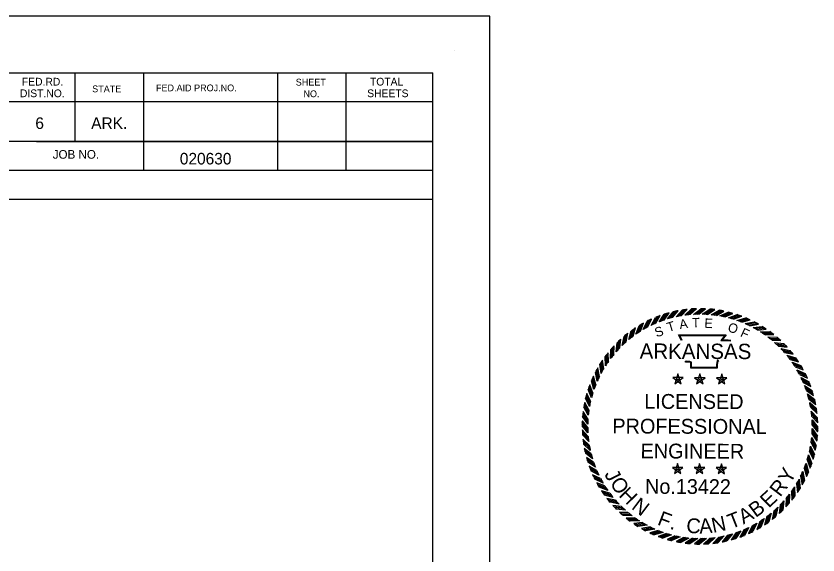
# Model space of a CAD drawing. Extents: x 759422 to 1402140, y 1662254 to 1956530.
# Drawn here: x 1401731.3 to 1402137.5, y 1956257.2 to 1956530.4 of the extents above; entities that cross this region are included whole.
import ezdxf

# ---------------------------------------------------------------- set-up
doc = ezdxf.new("R2010")
doc.units = 0
doc.layers.add('1', color=7, linetype='Continuous')
doc.layers.add('Default', color=7, linetype='Continuous')

# ---------------------------------------------------------------- blocks, each defined once
blk = doc.blocks.new('STAR')
at = {"layer": 'Default'}
for p, q in [((0.0587, 0.0188), (-0.059, 0.0189)), ((-0.0589, 0.0188), (0.0363, -0.0505)), ((-0.0001, 0.0615), (-0.0366, -0.0504)), ((-0.0365, -0.0503), (0.0589, 0.0188)), ((-0.0085, 0), (0.009, 0)), ((0.0362, -0.0503), (0, 0.0617)), ((0, 0.0063), (0, -0.0085))]:
    blk.add_line(p, q, dxfattribs=at)
blk = doc.blocks.new('RP')
at = {"layer": 'Default'}
for p, q in [((-0.0781, 1.2656), (0.003, 1.33)), ((-0.058, 1.2667), (0.0216, 1.3299)), ((-0.0375, 1.2674), (0.0405, 1.3294)), ((-0.0176, 1.2679), (0.059, 1.3287))]:
    blk.add_line(p, q, dxfattribs=at)
for radius, start, end in [(1.268, 90.79335, 93.53072), (1.33, 87.45624, 89.86992)]:
    blk.add_arc((0, 0), radius, start, end, dxfattribs=at)

msp = doc.modelspace()

# ---------------------------------------------------------------- linework, layer by layer
at = {"layer": '1'}
for p, q in [((1401953.38, 1956513.05), (1401953.38, 1956513.05)), ((1400347.07, 1956501.52), (1401942.43, 1956501.52)), ((1401761.13, 1956501.52), (1401761.13, 1956466.82)), ((1401795.83, 1956501.52), (1401795.83, 1956452.12)), ((1401863.73, 1956501.52), (1401863.73, 1956452.12)), ((1401898.43, 1956501.52), (1401898.43, 1956452.12)), ((1401942.43, 1955459.2), (1401942.43, 1956501.52)), ((1401942.43, 1956486.82), (1401726.93, 1956486.82)), ((1401942.43, 1956486.92), (1401942.43, 1956486.92)), ((1401942.43, 1956466.82), (1401726.93, 1956466.82)), ((1401741.73, 1956466.82), (1401942.43, 1956466.82)), ((1401942.43, 1956452.12), (1401531.13, 1956452.12)), ((1401726.93, 1956437.52), (1401942.43, 1956437.52))]:
    msp.add_line(p, q, dxfattribs=at)
msp.add_lwpolyline([(1401971.27, 1956530.36), (1400271.27, 1956530.36), (1400271.27, 1955430.36), (1401971.27, 1955430.36)], close=True, dxfattribs=at)
at = {"layer": 'Default'}
for points in [[(1402068.36, 1956365.8), (1402066.98, 1956368.82), (1402091.1, 1956368.76), (1402089.08, 1956366.23), (1402090.72, 1956366.25), (1402092.09, 1956366.26), (1402093.46, 1956366.1)], [(1402068.71, 1956365.96), (1402067.57, 1956368.44), (1402090.31, 1956368.38), (1402088.28, 1956365.84), (1402090.72, 1956365.86), (1402092.07, 1956365.88), (1402093.41, 1956365.72)], [(1402087.26, 1956355.62), (1402086.84, 1956355.29), (1402086.71, 1956354.79), (1402086.57, 1956353.54), (1402086.56, 1956351.87), (1402073.09, 1956351.92), (1402073.1, 1956354.17), (1402073.1, 1956354.67), (1402072.56, 1956354.84), (1402070.64, 1956354.85), (1402070.3, 1956355.37)], [(1402087.02, 1956355.92), (1402086.51, 1956355.51), (1402086.33, 1956354.86), (1402086.18, 1956353.56), (1402086.18, 1956352.26), (1402073.48, 1956352.3), (1402073.48, 1956354.17), (1402073.48, 1956354.95), (1402072.61, 1956355.22), (1402070.85, 1956355.23), (1402070.62, 1956355.57)]]:
    msp.add_lwpolyline(points, dxfattribs=at)

# ---------------------------------------------------------------- block references
for name, p, xscale, yscale, rotation in [('RP', (1402077.8, 1956322.35), 44.855502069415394, 44.85550206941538, 13.304199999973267), ('RP', (1402077.8, 1956322.35), 44.855502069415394, 44.855502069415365, 8.804199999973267), ('RP', (1402077.8, 1956322.35), 44.85550206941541, 44.85550206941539, 4.304199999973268), ('RP', (1402077.8, 1956322.35), 44.8555020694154, 44.85550206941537, -0.19580000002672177), ('RP', (1402077.8, 1956322.35), 44.8555020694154, 44.85550206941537, -4.695800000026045), ('RP', (1402077.8, 1956322.35), 44.85550206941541, 44.85550206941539, -9.195800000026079), ('RP', (1402077.8, 1956322.35), 44.855502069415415, 44.85550206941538, -13.695800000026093), ('RP', (1402077.8, 1956322.35), 44.855502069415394, 44.855502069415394, 26.804199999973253), ('RP', (1402077.8, 1956322.35), 44.85550206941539, 44.85550206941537, 22.30419999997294), ('RP', (1402077.8, 1956322.35), 44.855502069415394, 44.85550206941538, 17.80419999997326), ('RP', (1402077.8, 1956322.35), 44.85550206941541, 44.85550206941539, -18.195800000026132), ('RP', (1402077.8, 1956322.35), 44.8555020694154, 44.85550206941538, -22.69580000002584), ('RP', (1402077.8, 1956322.35), 44.855502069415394, 44.85550206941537, -27.19580000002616), ('RP', (1402077.8, 1956322.35), 44.85550206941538, 44.85550206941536, 31.30419999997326), ('RP', (1402077.8, 1956322.35), 44.85550206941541, 44.8555020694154, -31.695800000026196), ('RP', (1402077.8, 1956322.35), 44.85550206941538, 44.85550206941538, 40.304199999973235), ('RP', (1402077.8, 1956322.35), 44.85550206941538, 44.85550206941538, 35.80419999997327), ('RP', (1402077.8, 1956322.35), 44.8555020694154, 44.855502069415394, -36.195800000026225), ('RP', (1402077.8, 1956322.35), 44.85550206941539, 44.8555020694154, -40.69580000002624), ('RP', (1402077.8, 1956322.35), 44.85550206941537, 44.855502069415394, 44.80419999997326), ('RP', (1402077.8, 1956322.35), 44.85550206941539, 44.85550206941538, -45.195800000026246), ('RP', (1402077.8, 1956322.35), 44.8555020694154, 44.8555020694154, 49.304199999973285), ('RP', (1402077.8, 1956322.35), 44.85550206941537, 44.85550206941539, -49.695800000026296), ('RP', (1402077.8, 1956322.35), 44.8555020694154, 44.85550206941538, 53.804199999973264), ('RP', (1402077.8, 1956322.35), 44.85550206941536, 44.855502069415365, -54.1958000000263), ('RP', (1402077.8, 1956322.35), 44.85550206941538, 44.85550206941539, 58.304199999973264), ('RP', (1402077.8, 1956322.35), 44.85550206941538, 44.85550206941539, -58.695800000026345), ('RP', (1402077.8, 1956322.35), 44.85550206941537, 44.85550206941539, -63.19580000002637), ('RP', (1402077.8, 1956322.35), 44.85550206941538, 44.855502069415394, 62.804199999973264), ('STAR', (1402066.61, 1956346.21), 44.8555020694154, 44.85550206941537, -0.19580000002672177), ('STAR', (1402077.71, 1956346.17), 44.8555020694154, 44.85550206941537, -0.19580000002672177), ('STAR', (1402088.81, 1956346.13), 44.8555020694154, 44.85550206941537, -0.19580000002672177), ('RP', (1402077.8, 1956322.35), 44.85550206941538, 44.8555020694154, 67.30419999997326), ('RP', (1402077.8, 1956322.35), 44.85550206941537, 44.85550206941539, -67.6958000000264), ('RP', (1402077.8, 1956322.35), 44.85550206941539, 44.855502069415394, 71.80419999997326), ('RP', (1402077.8, 1956322.35), 44.85550206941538, 44.8555020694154, -72.19580000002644), ('RP', (1402077.8, 1956322.35), 44.85550206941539, 44.85550206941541, 76.30419999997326), ('RP', (1402077.8, 1956322.35), 44.85550206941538, 44.85550206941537, -76.69580000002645), ('RP', (1402077.8, 1956322.35), 44.85550206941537, 44.8555020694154, 80.80419999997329), ('RP', (1402077.8, 1956322.35), 44.85550206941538, 44.8555020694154, -81.19580000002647), ('RP', (1402077.8, 1956322.35), 44.855502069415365, 44.85550206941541, 85.30419999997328), ('RP', (1402077.8, 1956322.35), 44.85550206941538, 44.855502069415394, -85.69580000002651), ('RP', (1402077.8, 1956322.35), 44.85550206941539, 44.85550206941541, 89.80419999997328), ('RP', (1402077.8, 1956322.35), 44.85550206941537, 44.8555020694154, -90.19580000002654), ('RP', (1402077.8, 1956322.35), 44.85550206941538, 44.85550206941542, 94.30419999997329), ('RP', (1402077.8, 1956322.35), 44.85550206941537, 44.85550206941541, -94.69580000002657), ('RP', (1402077.8, 1956322.35), 44.85550206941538, 44.855502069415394, 98.8041999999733), ('RP', (1402077.8, 1956322.35), 44.85550206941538, 44.855502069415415, -99.19580000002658), ('RP', (1402077.8, 1956322.35), 44.85550206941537, 44.8555020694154, 103.30419999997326), ('RP', (1402077.8, 1956322.35), 44.85550206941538, 44.8555020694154, -103.69580000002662), ('RP', (1402077.8, 1956322.35), 44.85550206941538, 44.85550206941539, -108.19580000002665), ('RP', (1402077.8, 1956322.35), 44.85550206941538, 44.855502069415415, 107.80419999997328), ('RP', (1402077.8, 1956322.35), 44.85550206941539, 44.855502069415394, -112.69580000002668), ('RP', (1402077.8, 1956322.35), 44.85550206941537, 44.85550206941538, 112.3041999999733), ('STAR', (1402066.46, 1956300.71), 44.8555020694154, 44.85550206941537, -0.19580000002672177), ('STAR', (1402077.56, 1956300.68), 44.8555020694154, 44.85550206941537, -0.19580000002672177), ('STAR', (1402088.65, 1956300.64), 44.8555020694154, 44.85550206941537, -0.19580000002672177), ('RP', (1402077.8, 1956322.35), 44.85550206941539, 44.8555020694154, 116.80419999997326), ('RP', (1402077.8, 1956322.35), 44.85550206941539, 44.8555020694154, -121.69580000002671), ('RP', (1402077.8, 1956322.35), 44.85550206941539, 44.85550206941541, -117.19580000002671), ('RP', (1402077.8, 1956322.35), 44.855502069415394, 44.85550206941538, 121.30419999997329), ('RP', (1402077.8, 1956322.35), 44.8555020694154, 44.8555020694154, -126.19580000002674), ('RP', (1402077.8, 1956322.35), 44.85550206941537, 44.85550206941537, 125.80419999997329), ('RP', (1402077.8, 1956322.35), 44.85550206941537, 44.85550206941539, 130.3041999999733), ('RP', (1402077.8, 1956322.35), 44.85550206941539, 44.85550206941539, -130.6958000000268), ('RP', (1402077.8, 1956322.35), 44.855502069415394, 44.85550206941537, 134.80419999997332), ('RP', (1402077.8, 1956322.35), 44.85550206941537, 44.855502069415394, -135.19580000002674), ('RP', (1402077.8, 1956322.35), 44.85550206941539, 44.85550206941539, 139.30419999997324), ('RP', (1402077.8, 1956322.35), 44.85550206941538, 44.85550206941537, -139.69580000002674), ('RP', (1402077.8, 1956322.35), 44.85550206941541, 44.855502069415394, 143.8041999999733), ('RP', (1402077.8, 1956322.35), 44.85550206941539, 44.85550206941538, 148.3041999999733), ('RP', (1402077.8, 1956322.35), 44.85550206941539, 44.85550206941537, -148.69580000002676), ('RP', (1402077.8, 1956322.35), 44.85550206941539, 44.855502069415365, -144.19580000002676), ('RP', (1402077.8, 1956322.35), 44.8555020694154, 44.855502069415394, 152.8041999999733), ('RP', (1402077.8, 1956322.35), 44.8555020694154, 44.85550206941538, -157.6958000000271), ('RP', (1402077.8, 1956322.35), 44.85550206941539, 44.85550206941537, -153.1958000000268), ('RP', (1402077.8, 1956322.35), 44.8555020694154, 44.85550206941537, 157.3041999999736), ('RP', (1402077.8, 1956322.35), 44.85550206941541, 44.85550206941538, 161.80419999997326), ('RP', (1402077.8, 1956322.35), 44.855502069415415, 44.85550206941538, 166.3041999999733), ('RP', (1402077.8, 1956322.35), 44.855502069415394, 44.85550206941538, -166.69580000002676), ('RP', (1402077.8, 1956322.35), 44.855502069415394, 44.85550206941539, -162.19580000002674), ('RP', (1402077.8, 1956322.35), 44.8555020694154, 44.855502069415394, 170.8041999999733), ('RP', (1402077.8, 1956322.35), 44.8555020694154, 44.85550206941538, 175.3041999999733), ('RP', (1402077.8, 1956322.35), 44.85550206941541, 44.85550206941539, 179.8041999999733), ('RP', (1402077.8, 1956322.35), 44.8555020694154, 44.85550206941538, -175.69580000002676), ('RP', (1402077.8, 1956322.35), 44.85550206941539, 44.85550206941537, -171.19580000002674)]:
    msp.add_blockref(name, p, dxfattribs=dict(at, xscale=xscale, yscale=yscale, rotation=rotation))

# ---------------------------------------------------------------- texts
at = {"layer": '1'}
for s, height, p in [('FED.RD.', 3.91, (1401734.32, 1956495.12)), ('TOTAL', 3.91, (1401910.62, 1956495.12)), ('STATE', 3.42, (1401769.92, 1956491.72)), ('FED.AID PROJ.NO.', 3.42, (1401802.22, 1956492.22)), ('SHEET', 3.42, (1401873.02, 1956495.12)), ('DIST.NO.', 3.91, (1401733.32, 1956489.22)), ('NO.', 3.42, (1401876.92, 1956489.22)), ('SHEETS', 3.91, (1401909.22, 1956489.22)), ('6', 5.86, (1401741.12, 1956473.12)), ('ARK.', 5.861, (1401769.42, 1956473.12)), ('JOB NO.', 4.396, (1401749.92, 1956458.02)), ('020630', 5.862, (1401814.3, 1956455.12))]:
    msp.add_text(s, height=height, dxfattribs=at).set_placement(p)
at = {"layer": 'Default'}
for s, height, rotation, p in [('T', 4.76, 1.2831, (1402073.8, 1956372.54)), ('E', 4.76, 356.4762, (1402079.89, 1956372.37)), ('S', 4.76, 19.5768, (1402055.8, 1956367.42)), ('T', 4.76, 16.7057, (1402061.86, 1956370.12)), ('A', 4.76, 8.483, (1402067.65, 1956371.61)), ('O', 4.76, 341.026, (1402091.44, 1956370.7)), ('F', 4.76, 335.167, (1402097.84, 1956368.17)), ('ARKANSAS', 7.767, 359.8042, (1402047.21, 1956356.63)), ('LICENSED', 7.52, 359.8042, (1402049.54, 1956331.27)), ('PROFESSIONAL', 7.5196, 359.8042, (1402033.38, 1956318.75)), ('ENGINEER', 7.52, 359.8042, (1402047.66, 1956306.12)), ('J', 7.52, 297.2813, (1402029.19, 1956298.19)), ('Y', 7.52, 62.5392, (1402123.64, 1956292.84)), ('O', 7.52, 304.1899, (1402031.85, 1956293.57)), ('No.13422', 7.49, 359.8042, (1402049.97, 1956288.19)), ('H', 7.52, 314.7447, (1402036.29, 1956287.1)), ('R', 7.52, 52.7437, (1402118.39, 1956286.22)), ('E', 7.52, 44.306, (1402112.66, 1956280.62)), ('N', 7.52, 322.9417, (1402042.64, 1956280.81)), ('B', 7.52, 36.505, (1402106.02, 1956275.84)), ('F', 7.52, 339.0288, (1402055.76, 1956272.66)), ('T', 7.52, 21.4329, (1402093.52, 1956270.21)), ('A', 7.52, 28.8562, (1402099.78, 1956272.56)), ('C', 7.52, 356.1028, (1402070.68, 1956268.44)), ('A', 7.52, 3.9092, (1402077.58, 1956267.95)), ('N', 7.52, 12.0703, (1402084.45, 1956268.33)), ('.', 7.52, 344.7037, (1402062.18, 1956270.44))]:
    msp.add_text(s, height=height, rotation=rotation, dxfattribs=at).set_placement(p)

doc.saveas('drawing.dxf')
